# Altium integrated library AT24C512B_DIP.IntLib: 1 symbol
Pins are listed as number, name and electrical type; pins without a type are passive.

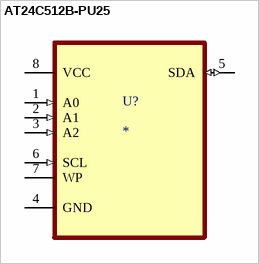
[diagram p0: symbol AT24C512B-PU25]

## AT24C512B-PU25
designator U?
EEPROM SERIAL 2.7-5.5V 512K, 24C512; Memory Size:512Kbit; Memory Configuration:64K x 8; Interface Type:Serial, 2-Wire; Clock Frequency:400kHz; Supply Voltage Range:1.8V to 3.6V; Memory Case Style:DIP; No. of Pins:8; Operating Temperature Range:-40Â°C to +85Â°C; SVHC:No SVHC (20-Jun-2011); Base Number:24; Device Marking:AT24C512B; Frequency:1MHz; IC Generic Number:24C512; Interface:I2C; Interface Type:Serial, I2C; Logic Function Number:512; Memory Configuration:64K x 8; Memory Size:512Kbit; Memory Type:EEPROM; Memory Voltage Vcc:1.8V; Operating Temperature Max:+85Â°C; Operating Temperature Min:-40Â°C; Package / Case:DIP; Supply Voltage Max:5.5V; Supply Voltage Min:2.5V; Termination Type:Through Hole; Voltage Vcc:5.5V; MF: Microchip; MP: AT24C512B-PU25
footprint DIP254P762X533-8
pins: 1 A0 (in), 2 A1 (in), 3 A2 (in), 4 GND, 5 SDA (io), 6 SCL (in), 7 WP, 8 VCC (power)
